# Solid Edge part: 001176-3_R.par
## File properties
Last saved by: morva
Revision: 82
Accuracy: 0.990
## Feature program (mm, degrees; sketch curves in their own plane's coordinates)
body "unnamed Body 1"
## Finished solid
Body 1: solid body, 48 faces, 136 edges, 88 vertices.
  Faces by surface: cylinder 26, plane 14, spline 8
  Edges by curve: line 64, circle 48, curve on surface 24
Bounding box of the edges (mm; curved faces can reach further): 15.017 x 16.177 x 21.585, from (427.0823, 370.0162, 160.4857) to (442.0997, 386.1931, 182.0708).
Cylindrical faces by radius (mm): R0.7366 x3, R1 x2, R1.5 x4, R1.517 x1, R1.5585 x1, R2.2366 x3, R3 x2, R3.5 x3, R3.75 x3, R6 x4
Planar faces by outward normal: oblique 14
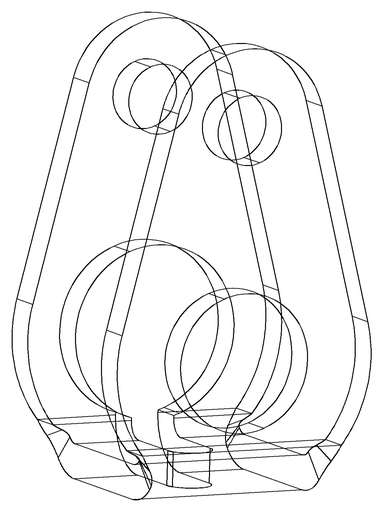
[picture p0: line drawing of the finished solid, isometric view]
